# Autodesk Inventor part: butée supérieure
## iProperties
Created: 2011-09
Part Number: butée supérieure
Document SubType Name: Modeling
Designer: Dominique
Author: Dominique
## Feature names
1. Extrusion1
2. Extrusion2
3. Perçage1 [Hole]
4. Perçage2 [Hole]
